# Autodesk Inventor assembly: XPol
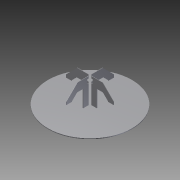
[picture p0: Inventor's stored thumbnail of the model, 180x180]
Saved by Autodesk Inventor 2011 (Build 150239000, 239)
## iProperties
Created: 2014-11
Part Number: XPol
Document SubType Name: Assembly
Designer: Evgeny
Author: Evgeny
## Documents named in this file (3)
- D:\Autodesk Invertor 2011\Projects2014\Antenna\Xpol\XPol.iam
- D:\Autodesk Invertor 2011\Projects2014\Antenna\Xpol\XPref.ipt
- D:\Autodesk Invertor 2011\Projects2014\Antenna\Xpol\Xp1.ipt
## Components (5 placed, 2 different names)
1. XPref:1 — Совмещение:1, Совмещение:2, Совмещение:3, Совмещение:4, Совмещение:5, Совмещение:6, Совмещение:7, Совмещение:8, Совмещение:9, Совмещение:10, Совмещение:11, Совмещение:12
2. Xp1:1 — Совмещение:1, Совмещение:2, Совмещение:3
3. Xp1:2 — Совмещение:4, Совмещение:5, Совмещение:6
4. Xp1:3 — Совмещение:7, Совмещение:8, Совмещение:9
5. Xp1:4 — Совмещение:10, Совмещение:11, Совмещение:12
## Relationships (12: Mate 12)
- Совмещение:1 [Mate]: XPref:1 ↔ Xp1:1
- Совмещение:2 [Mate]: XPref:1 ↔ Xp1:1
- Совмещение:3 [Mate]: XPref:1 ↔ Xp1:1
- Совмещение:4 [Mate]: XPref:1 ↔ Xp1:2
- Совмещение:5 [Mate]: XPref:1 ↔ Xp1:2
- Совмещение:6 [Mate]: XPref:1 ↔ Xp1:2
- Совмещение:7 [Mate]: XPref:1 ↔ Xp1:3
- Совмещение:8 [Mate]: XPref:1 ↔ Xp1:3
- Совмещение:9 [Mate]: XPref:1 ↔ Xp1:3
- Совмещение:10 [Mate]: XPref:1 ↔ Xp1:4
- Совмещение:11 [Mate]: XPref:1 ↔ Xp1:4
- Совмещение:12 [Mate]: XPref:1 ↔ Xp1:4
